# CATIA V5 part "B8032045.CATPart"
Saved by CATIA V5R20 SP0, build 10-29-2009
Part number: B8032045
Revision: 5
Definition: design
Nomenclature: B8032045
Source: made
Description: NOT SPECIFIED
Bounding box of the stored display mesh (mm): x -16 to 16, y -16 to 16, z 0 to 45
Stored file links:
  C:\Users\Utente\Desktop\3D files B803\B8032045.CATPart
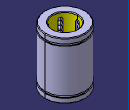
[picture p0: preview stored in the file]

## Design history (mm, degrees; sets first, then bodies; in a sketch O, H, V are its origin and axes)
Body1 "MANIFOLD_SOLID_BREP #38" (main body)
  Solid1: solid without history
Body2 "MANIFOLD_SOLID_BREP #76"
  Solid2: solid without history
Body3 "MANIFOLD_SOLID_BREP #114"
  Solid3: solid without history
Body4 "MANIFOLD_SOLID_BREP #152"
  Solid4: solid without history
Body5 "MANIFOLD_SOLID_BREP #190"
  Solid5: solid without history
Body6 "MANIFOLD_SOLID_BREP #228"
  Solid6: solid without history
Body7 "MANIFOLD_SOLID_BREP #266"
  Solid7: solid without history
Body8 "MANIFOLD_SOLID_BREP #304"
  Solid8: solid without history
Body9 "MANIFOLD_SOLID_BREP #2066"
  Solid9: solid without history
Body10 "MANIFOLD_SOLID_BREP #2104"
  Solid10: solid without history
Body11 "MANIFOLD_SOLID_BREP #2142"
  Solid11: solid without history
Body12 "MANIFOLD_SOLID_BREP #2180"
  Solid12: solid without history
Body13 "MANIFOLD_SOLID_BREP #2218"
  Solid13: solid without history
Body14 "MANIFOLD_SOLID_BREP #2256"
  Solid14: solid without history
Body15 "MANIFOLD_SOLID_BREP #2294"
  Solid15: solid without history
Body16 "MANIFOLD_SOLID_BREP #2332"
  Solid16: solid without history
Body17 "MANIFOLD_SOLID_BREP #2370"
  Solid17: solid without history
Body18 "MANIFOLD_SOLID_BREP #2408"
  Solid18: solid without history
Body19 "MANIFOLD_SOLID_BREP #2446"
  Solid19: solid without history
Body20 "MANIFOLD_SOLID_BREP #2484"
  Solid20: solid without history
Body21 "MANIFOLD_SOLID_BREP #2522"
  Solid21: solid without history
Body22 "MANIFOLD_SOLID_BREP #2560"
  Solid22: solid without history
Body23 "MANIFOLD_SOLID_BREP #2598"
  Solid23: solid without history
Body24 "MANIFOLD_SOLID_BREP #2636"
  Solid24: solid without history
Body25 "MANIFOLD_SOLID_BREP #2674"
  Solid25: solid without history
Body26 "MANIFOLD_SOLID_BREP #2712"
  Solid26: solid without history
Body27 "MANIFOLD_SOLID_BREP #2750"
  Solid27: solid without history
Body28 "MANIFOLD_SOLID_BREP #2788"
  Solid28: solid without history
Body29 "MANIFOLD_SOLID_BREP #2826"
  Solid29: solid without history
Body30 "MANIFOLD_SOLID_BREP #2864"
  Solid30: solid without history
Body31 "MANIFOLD_SOLID_BREP #2902"
  Solid31: solid without history
Body32 "MANIFOLD_SOLID_BREP #2940"
  Solid32: solid without history
Body33 "MANIFOLD_SOLID_BREP #2978"
  Solid33: solid without history
Body34 "MANIFOLD_SOLID_BREP #3016"
  Solid34: solid without history
Body35 "MANIFOLD_SOLID_BREP #3054"
  Solid35: solid without history
Body36 "MANIFOLD_SOLID_BREP #3092"
  Solid36: solid without history
Body37 "MANIFOLD_SOLID_BREP #3130"
  Solid37: solid without history
Body38 "MANIFOLD_SOLID_BREP #3168"
  Solid38: solid without history
Body39 "MANIFOLD_SOLID_BREP #3206"
  Solid39: solid without history
Body40 "MANIFOLD_SOLID_BREP #3244"
  Solid40: solid without history
Body41 "MANIFOLD_SOLID_BREP #3282"
  Solid41: solid without history
Body42 "MANIFOLD_SOLID_BREP #3320"
  Solid42: solid without history
Body43 "MANIFOLD_SOLID_BREP #3358"
  Solid43: solid without history
Body44 "MANIFOLD_SOLID_BREP #3396"
  Solid44: solid without history
Body45 "MANIFOLD_SOLID_BREP #3434"
  Solid45: solid without history
Body46 "MANIFOLD_SOLID_BREP #3472"
  Solid46: solid without history
Body47 "MANIFOLD_SOLID_BREP #3510"
  Solid47: solid without history
Body48 "MANIFOLD_SOLID_BREP #3548"
  Solid48: solid without history
Body49 "MANIFOLD_SOLID_BREP #3586"
  Solid49: solid without history
Body50 "MANIFOLD_SOLID_BREP #3624"
  Solid50: solid without history
Body51 "MANIFOLD_SOLID_BREP #3662"
  Solid51: solid without history
Body52 "MANIFOLD_SOLID_BREP #3700"
  Solid52: solid without history
Body53 "MANIFOLD_SOLID_BREP #3738"
  Solid53: solid without history
Body54 "MANIFOLD_SOLID_BREP #3776"
  Solid54: solid without history
Body55 "MANIFOLD_SOLID_BREP #3814"
  Solid55: solid without history
Body56 "MANIFOLD_SOLID_BREP #3852"
  Solid56: solid without history
Body57 "MANIFOLD_SOLID_BREP #3890"
  Solid57: solid without history
Body58 "MANIFOLD_SOLID_BREP #3928"
  Solid58: solid without history
Body59 "MANIFOLD_SOLID_BREP #3966"
  Solid59: solid without history
Body60 "MANIFOLD_SOLID_BREP #4004"
  Solid60: solid without history
Body61 "MANIFOLD_SOLID_BREP #4042"
  Solid61: solid without history
Body62 "MANIFOLD_SOLID_BREP #4080"
  Solid62: solid without history
Body63 "MANIFOLD_SOLID_BREP #4118"
  Solid63: solid without history
Body64 "MANIFOLD_SOLID_BREP #4156"
  Solid64: solid without history
Body65 "MANIFOLD_SOLID_BREP #4194"
  Solid65: solid without history
Body66 "MANIFOLD_SOLID_BREP #4232"
  Solid66: solid without history
Body67 "MANIFOLD_SOLID_BREP #4270"
  Solid67: solid without history
Body68 "MANIFOLD_SOLID_BREP #4308"
  Solid68: solid without history
Body69 "MANIFOLD_SOLID_BREP #4346"
  Solid69: solid without history
Body70 "MANIFOLD_SOLID_BREP #4384"
  Solid70: solid without history
Body71 "MANIFOLD_SOLID_BREP #4422"
  Solid71: solid without history
Body72 "MANIFOLD_SOLID_BREP #4460"
  Solid72: solid without history
Body73 "MANIFOLD_SOLID_BREP #4498"
  Solid73: solid without history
